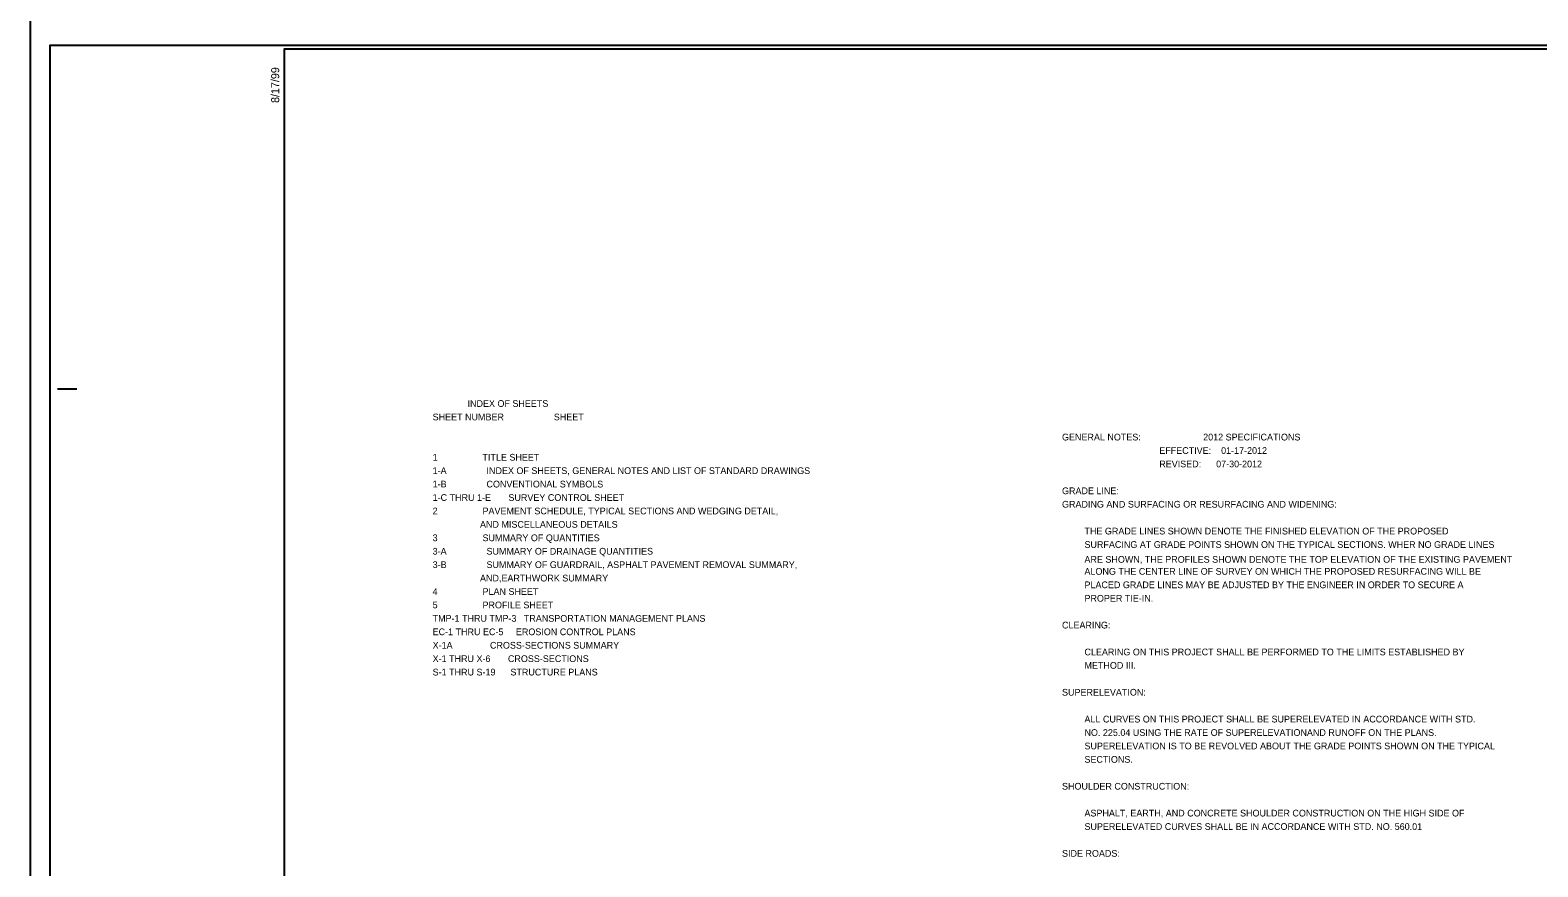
# Model space of a CAD drawing. Extents: x 1664524 to 1666208, y 587901 to 592296.
# Drawn here: x 1664524 to 1665512, y 590638 to 591186 of the extents above; entities that cross this region are included whole.
import ezdxf

# ---------------------------------------------------------------- set-up
doc = ezdxf.new("R2010")
doc.units = 0
for name, color, linetype in [('Old_Level_11', 7, 'Continuous'), ('Prop Horizontal Alignment Tick Large', 7, 'Continuous'), ('Prop Horizontal Alignment Tick Small', 7, 'Continuous'), ('Sheet Cutting Line CELL', 7, 'Continuous'), ('Sheet Plan CELL', 7, 'Continuous')]:
    doc.layers.add(name, color=color, linetype=linetype)

msp = doc.modelspace()

# ---------------------------------------------------------------- linework, layer by layer
at = {"layer": 'Prop Horizontal Alignment Tick Large'}
msp.add_lwpolyline([(1664536.76, 590121.35), (1666202.76, 590121.35), (1666202.76, 591176.35), (1664536.76, 591176.35)], close=True, dxfattribs=at)
at = {"layer": 'Prop Horizontal Alignment Tick Small'}
msp.add_lwpolyline([(1664523.76, 590101.35), (1666207.26, 590101.35), (1666207.26, 591196.35), (1664523.76, 591196.35)], close=True, dxfattribs=at)
at = {"layer": 'Sheet Cutting Line CELL'}
msp.add_line((1664523.76, 591196.35), (1664523.76, 590101.35), dxfattribs=at)
at = {"layer": 'Sheet Plan CELL'}
for p, q in [((1664690.26, 591173.85), (1664690.26, 591173.85)), ((1664541.76, 590951.35), (1664554.26, 590951.35))]:
    msp.add_line(p, q, dxfattribs=at)
msp.add_lwpolyline([(1666190.26, 591173.85), (1664690.26, 591173.85), (1664690.26, 590123.85), (1666190.26, 590123.85)], close=True, dxfattribs=at)

# ---------------------------------------------------------------- texts
at = {"layer": 'Old_Level_11'}
for s, p in [('              INDEX OF SHEETS ', (1664787.59, 590939.49)), ('SHEET NUMBER                    SHEET', (1664787.59, 590930.69)), ('GENERAL NOTES:                         2012 SPECIFICATIONS', (1665200.17, 590917.49)), ('                                       EFFECTIVE:    01-17-2012', (1665200.17, 590908.69)), ('1                  TITLE SHEET ', (1664787.59, 590904.29)), ('1-A                INDEX OF SHEETS, GENERAL NOTES AND LIST OF STANDARD DRAWINGS ', (1664787.59, 590895.49)), ('                                       REVISED:      07-30-2012', (1665200.17, 590899.89)), ('1-B                CONVENTIONAL SYMBOLS', (1664787.59, 590886.69)), ('GRADE LINE:  ', (1665200.17, 590882.29)), ('2                  PAVEMENT SCHEDULE, TYPICAL SECTIONS AND WEDGING DETAIL,', (1664787.59, 590869.09)), ('GRADING AND SURFACING OR RESURFACING AND WIDENING:  ', (1665200.17, 590873.49)), ('                   AND MISCELLANEOUS DETAILS', (1664787.59, 590860.29)), ('         THE GRADE LINES SHOWN DENOTE THE FINISHED ELEVATION OF THE PROPOSED ', (1665200.17, 590855.89)), ('3                  SUMMARY OF QUANTITIES ', (1664787.59, 590851.49)), ('         SURFACING AT GRADE POINTS SHOWN ON THE TYPICAL SECTIONS. WHER NO GRADE LINES ', (1665200.17, 590847.09)), ('3-A                SUMMARY OF DRAINAGE QUANTITIES ', (1664787.59, 590842.69)), ('         ARE SHOWN, THE PROFILES SHOWN DENOTE THE TOP ELEVATION OF THE EXISTING PAVEMENT', (1665200.17, 590837.35)), ('3-B                SUMMARY OF GUARDRAIL, ASPHALT PAVEMENT REMOVAL SUMMARY, ', (1664787.59, 590833.89)), ('         ALONG THE CENTER LINE OF SURVEY ON WHICH THE PROPOSED RESURFACING WILL BE', (1665200.17, 590829.49)), ('4                  PLAN SHEET ', (1664787.59, 590816.29)), ('                   AND,EARTHWORK SUMMARY', (1664787.59, 590825.09)), ('         PLACED GRADE LINES MAY BE ADJUSTED BY THE ENGINEER IN ORDER TO SECURE A ', (1665200.17, 590820.69)), ('5                  PROFILE SHEET  ', (1664787.59, 590807.49)), ('         PROPER TIE-IN.  ', (1665200.17, 590811.89)), ('TMP-1 THRU TMP-3   TRANSPORTATION MANAGEMENT PLANS', (1664787.59, 590798.69)), ('EC-1 THRU EC-5     EROSION CONTROL PLANS ', (1664787.59, 590789.89)), ('CLEARING:  ', (1665200.17, 590794.29)), ('X-1A               CROSS-SECTIONS SUMMARY', (1664787.59, 590781.09)), ('         CLEARING ON THIS PROJECT SHALL BE PERFORMED TO THE LIMITS ESTABLISHED BY ', (1665200.17, 590776.69)), ('X-1 THRU X-6       CROSS-SECTIONS ', (1664787.59, 590772.29)), ('         METHOD III.', (1665200.17, 590767.89)), ('S-1 THRU S-19      STRUCTURE PLANS', (1664787.59, 590763.49)), ('SUPERELEVATION:  ', (1665200.17, 590750.29)), ('         ALL CURVES ON THIS PROJECT SHALL BE SUPERELEVATED IN ACCORDANCE WITH STD. ', (1665200.17, 590732.69)), ('         NO. 225.04 USING THE RATE OF SUPERELEVATIONAND RUNOFF ON THE PLANS.', (1665200.17, 590723.89)), ('         SUPERELEVATION IS TO BE REVOLVED ABOUT THE GRADE POINTS SHOWN ON THE TYPICAL ', (1665200.17, 590715.09)), ('         SECTIONS.  ', (1665200.17, 590706.29)), ('SHOULDER CONSTRUCTION:  ', (1665200.17, 590688.69)), ('         ASPHALT, EARTH, AND CONCRETE SHOULDER CONSTRUCTION ON THE HIGH SIDE OF', (1665200.17, 590671.09)), ('         SUPERELEVATED CURVES SHALL BE IN ACCORDANCE WITH STD. NO. 560.01', (1665200.17, 590662.29)), ('SIDE ROADS:  ', (1665200.17, 590644.69))]:
    msp.add_text(s, height=4.4, rotation=360, dxfattribs=at).set_placement(p)
msp.add_text('1-C THRU 1-E       SURVEY CONTROL SHEET', height=4.4, dxfattribs=at).set_placement((1664787.59, 590877.89))
at = {"layer": 'Sheet Plan CELL'}
msp.add_text('8/17/99', height=5.25, rotation=90, dxfattribs=at).set_placement((1664687.01, 591138.65))

doc.saveas('drawing.dxf')
